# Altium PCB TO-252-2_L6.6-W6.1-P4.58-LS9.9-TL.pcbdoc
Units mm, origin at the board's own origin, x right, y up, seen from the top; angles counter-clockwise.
Board outline 23.92 x 19.39 mm, 2 copper layers (Top Layer, Bottom Layer), stack 0.07 mm thick; 1 components, 0 nets, 3 pads, 0 vias.
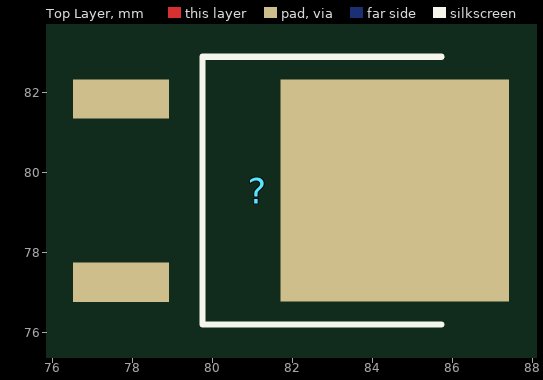
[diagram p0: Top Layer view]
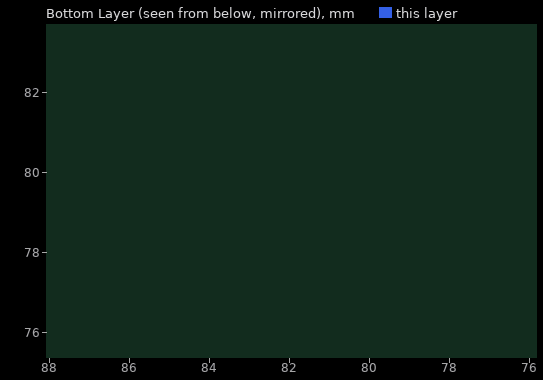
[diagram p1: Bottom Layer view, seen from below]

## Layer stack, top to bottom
Top Solder Mask Layer: solder mask 0.01, Dk 3.3
Top Layer: signal copper 0.035
Bottom Layer: signal copper 0.035
Bottom Solder Mask Layer: solder mask 0.01, Dk 3.3

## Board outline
93.769,69.85 69.85,69.85 69.85,89.242 93.769,89.242

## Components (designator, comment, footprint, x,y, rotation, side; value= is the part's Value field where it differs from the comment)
? "TO-252-2_L6.6-W6.1-P4.58-LS9.9-TL" TO-252-2_L6.6-W6.1-P4.58-LS9.9-TL 81.14,79.546 r0 top

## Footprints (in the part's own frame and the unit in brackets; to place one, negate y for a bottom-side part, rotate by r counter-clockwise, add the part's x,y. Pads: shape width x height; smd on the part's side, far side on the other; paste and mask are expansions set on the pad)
TO-252-2_L6.6-W6.1-P4.58-LS9.9-TL [mm]
  rect 2.409x0.979 smd paste+0 mask+0.051: 1(-3.424,2.29) 3(-3.423,-2.29)
  rect 5.711x5.548 smd paste+0 mask+0.051: 2(3.424,0)
  silkscreen extent -1.38,-3.35 4.58,3.35

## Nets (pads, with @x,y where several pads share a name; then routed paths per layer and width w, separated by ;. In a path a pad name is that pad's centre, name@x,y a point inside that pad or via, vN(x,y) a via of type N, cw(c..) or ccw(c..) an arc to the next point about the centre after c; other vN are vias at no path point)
pads on no net: ?.1 ?.2 ?.3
